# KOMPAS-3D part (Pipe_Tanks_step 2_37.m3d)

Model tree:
1. X Axis
2. Y Axis
3. Z Axis  (labels: Pipe Dn 50; Valve Dy 50)
     Òîëùèíà ñòåíêè 1 = 1

Referenced files in C:\Documents and Settings\kashirsky\Мои документы\Camtasia Studio\Pipelines3D\Tanks\: Tanks_step 2.a3d
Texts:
  Pipe Dn 50
  Steel ASTM A295
  Three Point Plane
  Plane at Angle
  Line and Point Plane
  Axis through Two Vertices
  Axis of Feature
  Axis of Conical Surface
  Axis through Edge
  Trim by Surface
  Trim by Sketch
  Feature with No History
  Intersection Axis of Two Planes
  Two Line Plane
  Line and Face Plane
  Bend by line
  Hole in sheet body
  Cut in sheet body
  Point in CM
  Linear Dimension from Line to Point
  Surface Finish Symbol
  Geometric Tolerance Symbol
  Leader #1
  Leader #2
  Leader #3
  Shape Deviations and Datum
  Node point number
  Mark of coordination axis
  Node point designation
  Mark/Reference designation with leader
  Mark/reference designation on line
  Mark/Reference designation without leader
  Valve Dy 50
  Plane of section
